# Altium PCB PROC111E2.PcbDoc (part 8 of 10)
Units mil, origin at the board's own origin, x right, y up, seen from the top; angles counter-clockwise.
Board outline 7700 x 2300 mil, 6 copper layers (Top Layer, GND 1, SIG 1, SIG 2, GND 2, Bottom Layer), stack 78.711 mil thick; 767 components, 596 nets, 2755 pads, 1578 vias.
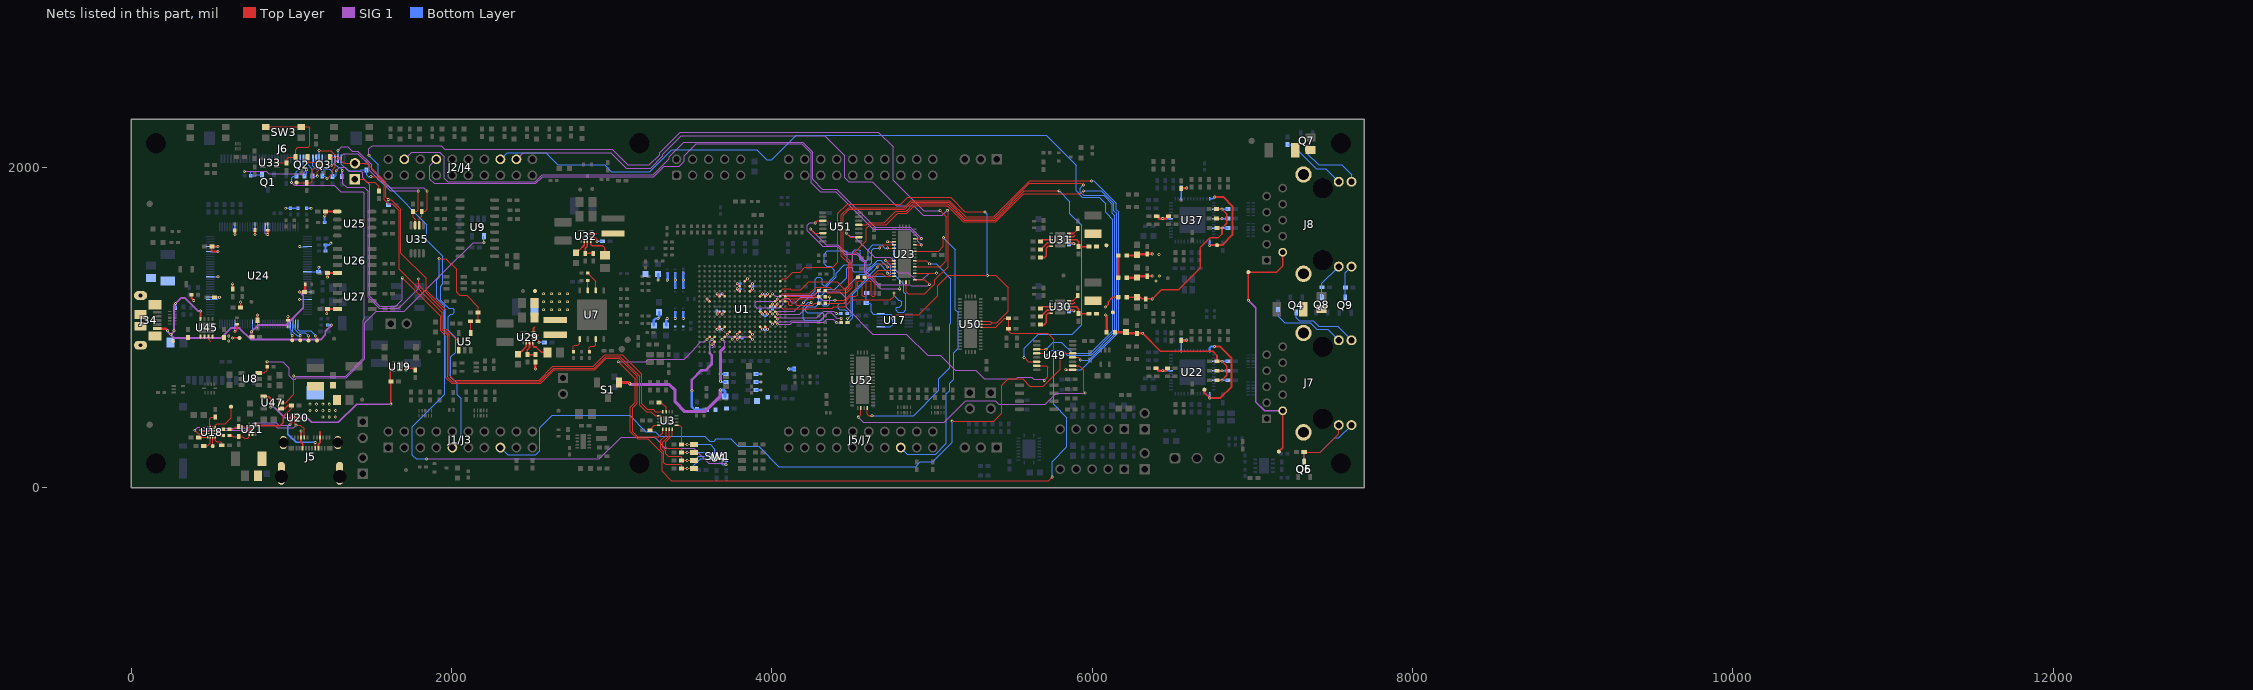
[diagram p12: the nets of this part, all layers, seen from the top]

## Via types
v1: diameter 18, hole 8, Top Layer to Bottom Layer, tented both sides, 1474 vias
v2: diameter 19.68, hole 7.87, Top Layer to Bottom Layer, tented both sides, 104 vias

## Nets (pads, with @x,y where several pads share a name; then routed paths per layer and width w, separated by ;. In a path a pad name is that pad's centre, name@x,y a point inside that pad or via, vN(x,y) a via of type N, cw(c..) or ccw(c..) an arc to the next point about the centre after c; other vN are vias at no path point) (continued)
PR0_PRU0_GPIO3: U1.J17 U23.5 | length 1520.8
  Top Layer w4: U1.J17@4051.07,1130.83 4065.96,1115.93 4114.06,1115.93
  Top Layer w5.3: 4114.06,1115.93 4267.37,1115.93 4270.36,1118.93 4376.37,1118.93 4385.74,1128.3 4454.83,1128.3 4498.62,1172.08 4739.09,1172.08 4762.04,1195.03 v1(4762.04,1215.27) ; v1(4720.59,1535.24) U23.5@4762.24,1535.24
  Bottom Layer w5.3: v1(4720.59,1535.24) 4741.8,1535.24 4765.63,1511.4 4765.63,1327.07 4824.32,1268.39 4824.32,1220.19 4834.95,1209.56 4834.95,1109.8 4821.54,1096.38 4785.96,1096.38 4775,1107.34 4775,1121.6 4780,1126.6 4793.49,1126.6 4809.6,1142.71 4809.6,1159.77 4798.17,1171.21 4792.65,1171.21 4761.31,1202.54 4761.31,1214.54 v1(4762.04,1215.27)
PR0_PRU0_GPIO3_MUX: J2/J4.19 U23.35 | length 3903.5
  Top Layer w5.3: U23.35@4892.17,1554.92 v1(4933.82,1554.92)
  SIG 1 w4.75: J2/J4.19@1704.17,2050 1749.17,2095 1925,2095 1952.52,2067.48 1952.52,1931.18 1974.46,1909.24 2521.06,1909.24 2566.14,1954.33 3259.33,1954.33 3358.59,2053.59 3358.59,2064.84 3449.94,2156.19 4191.54,2156.19 4255,2092.73 4255,1924.04 4315.04,1864 4404.5,1864 4643.67,1624.83 4863.91,1624.83 v1(4933.82,1554.92)
PR0_PRU0_GPIO4: U1.K16 U23.6 | length 1519.2
  Top Layer w5.3: v1(4670.59,1495.87) 4690.28,1515.55 U23.6@4762.24,1515.55
  Top Layer w10: U1.K16@4019.57,1099.33 v1(4035.32,1083.58)
  SIG 1 w4.75: v1(4035.32,1083.58) 4171.86,1083.58 v1(4244.93,1156.66)
  Bottom Layer w5.3: v1(4244.93,1156.66) 4226.95,1156.66 4195.86,1125.57 4195.86,1052.83 4204.94,1043.75 4310.25,1043.75 4321.85,1055.35 4321.85,1083.42 4312.51,1092.76 4219.07,1092.76 4211.79,1100.03 4211.79,1121.09 4220.2,1129.5 4273.31,1129.5 4291.03,1147.23 4291.03,1229.74 4312.18,1250.88 4336.11,1250.88 4400.6,1315.37 4400.6,1339.3 4452.05,1390.76 4609.04,1390.76 4623.28,1405 4623.28,1482.76 4636.39,1495.87 v1(4670.59,1495.87)
PR0_PRU0_GPIO4_MUX: J2/J4.17 U23.33 | length 3771.4
  Top Layer w5.3: U23.33@4892.17,1515.55 v1(4934.43,1515.55)
  SIG 1 w4.75: J2/J4.17@1904.17,2050 1863.41,2009.24 1863.41,1926.94 1891.16,1899.19 2525.22,1899.19 2568.25,1942.22 3261.43,1942.22 3326.48,2007.27 3421.87,2007.27 3451.39,2036.79 3451.39,2071.86 3525.68,2146.14 4187.37,2146.14 4244.93,2088.58 4244.93,1903.06 4300.49,1847.5 4399,1847.5 4631.72,1614.78 4859.05,1614.78 4911.11,1562.72 4911.11,1538.87 v1(4934.43,1515.55)
PR0_PRU0_GPIO5: U1.G17 U49.4 | length 4282.4
  Top Layer w4: U1.G17@4051.07,1193.82 4066.82,1209.57 4114.06,1209.57
  Top Layer w5.3: 4114.06,1209.57 4233.8,1209.57 4276.4,1252.16 4360,1252.16 4377.29,1234.87 4468.46,1234.87 4490.12,1256.53 4490.12,1412.6 4444.48,1458.25 4444.48,1699.98 4482.35,1737.85 4828.85,1737.85 4872.76,1781.76 5102.38,1781.76 5204.14,1680.01 5388.26,1680.01 5608,1899.74 5935.26,1899.74 v1(5945,1890) ; U49.4@5652.8,838.02 5696.58,838.02 v1(5711.38,823.23)
  Bottom Layer w5.3: v1(5711.38,823.23) 5745.7,857.55 5814.73,857.55 5845,827.28 5993.25,827.28 6141.42,975.45 6141.42,1697.14 6125.06,1713.5 6125.06,1769.96 6070.69,1824.33 5945.45,1824.33 5924.62,1845.16 5924.62,1869.62 v1(5945,1890)
PR0_PRU0_GPIO5_MUX: J2/J4.13 U49.3 | length 5659.9
  Top Layer w5.3: U49.3@5652.8,863.61 v1(5711.38,863.61)
  Bottom Layer w5.3: J2/J4.13@2304.17,2050 2345.21,2091.04 2587.3,2091.04 2663.17,2015.17 2954.83,2015.17 2996.5,1973.5 3237,1973.5 3374.75,2111.25 3906.14,2111.25 3968.7,2048.69 3999.85,2048.69 4152.49,2201.32 5711.87,2201.32 5899.18,2014.02 5899.18,1852.75 5938.19,1813.73 6043.16,1813.73 6083.45,1773.44 6083.45,1719.28 6129.52,1673.21 6129.52,1531.91 6129.4,1531.79 6129.4,978.42 5988.86,837.88 5877.94,837.88 5807.09,908.73 5756.49,908.73 v1(5711.38,863.61)
PR0_PRU0_GPIO6: U1.K15 U23.7 | length 1517.1
  Top Layer w5.3: v1(4720.59,1495.87) U23.7@4762.24,1495.87
  Top Layer w10: U1.K15@3988.08,1099.33 v1(4003.83,1083.58)
  SIG 1 w4.75: v1(4003.83,1083.58) 4020.24,1100 4140.09,1100 v1(4196.74,1156.66)
  Bottom Layer w5.3: v1(4196.74,1156.66) 4270.24,1230.15 4270.24,1302.02 4281.65,1313.43 4300,1313.43 4312.89,1300.54 4312.89,1270.44 4321.85,1261.48 4331.72,1261.48 4390,1319.76 4390,1358.24 4366.43,1381.81 4341.25,1381.81 4325,1398.06 4325,1458.62 4345.5,1479.12 4461.67,1479.12 4469.35,1471.45 4469.35,1413.42 4477.77,1405 4496.97,1405 4504.23,1412.26 4504.23,1474.23 4516.68,1486.68 4543.64,1486.68 4550,1480.32 4550,1425.91 4560.91,1415 4590,1415 4600.62,1425.62 4600.62,1486.68 4629.34,1515.39 4685.27,1515.39 4704.79,1495.87 v1(4720.59,1495.87)
PR0_PRU0_GPIO6_MUX: J5/J7.48 U23.31 | length 1927.2
  Top Layer w5.3: U23.31@4892.17,1476.18 5040,1476.18 5070,1506.18 v1(5070,1560.88)
  Bottom Layer w5.3: J5/J7.48@4804.17,250 4845.21,208.96 5021.17,208.96 5089.4,277.19 5089.4,584.4 5109.02,604.02 5109.02,651.44 5135.6,678.02 5135.6,843.47 5161.9,869.76 5161.9,1094.21 5145.12,1110.98 5145.12,1485.75 v1(5070,1560.88)
PR0_PRU0_GPIO8: U1.G15 U49.7 | length 2172.1
  Top Layer w5.3: U49.7@5652.8,761.25 5713.35,761.25 5722.21,752.39 5722.21,691.43 v1(5700.39,669.61)
  Top Layer w10: U1.G15@3988.08,1193.82 v1(4003.83,1209.57)
  SIG 1 w4.75: v1(4003.83,1209.57) 4019.2,1194.19 4041.69,1194.19 4047.02,1199.52 4262.49,1199.52 4286.06,1223.08 4422.81,1223.08 4462.51,1183.37 4462.51,1125.71 4630.59,957.64 4839.34,957.64 4971.11,825.87 5050.22,825.87 5142.89,733.2 5273.18,733.2 5326.71,679.67 5526.97,679.67 5535.37,688.07 5622.92,688.07 5635,676 5694,676 v1(5700.39,669.61)
PR0_PRU0_GPIO8_MUX: U49.6 U51.13 | length 2884
  Top Layer w5.3: U51.13@4542.2,1640.71 4590,1640.71 4603.53,1654.23 4700.73,1654.23 4772,1725.5 4837.5,1725.5 4883.16,1771.16 5097.99,1771.16 5199.75,1669.41 5392.65,1669.41 5576.49,1853.25 v1(5793.08,1853.25) ; v1(5574.59,812.43) 5600.18,786.84 U49.6@5652.8,786.84
  Bottom Layer w5.3: v1(5574.59,812.43) 5574.59,869.86 5663.53,958.8 5875.3,958.8 5933.8,1017.3 5933.8,1638 5860.24,1711.56 5860.24,1786.09 v1(5793.08,1853.25)
PR0_PRU0_GPIO9: U1.F17 U49.9 | length 4170
  Top Layer w4: U1.F17@4051.07,1225.32 4066.82,1241.06 4113.02,1241.06 4114.06,1240.02
  Top Layer w5.3: 4114.06,1240.02 4119.55,1234.53 4178.39,1234.53 4228.04,1284.18 4376.58,1284.18 4376.91,1284.5 4393.08,1284.5 4393.4,1284.18 4406.06,1284.18 4444.77,1245.47 4464.07,1245.47 4479.52,1260.92 4479.52,1399.39 4433.88,1445.04 4433.88,1704.37 4477.96,1748.45 4821.38,1748.45 4865.29,1792.36 5106.77,1792.36 5208.53,1690.61 5383.87,1690.61 5608.26,1915 v1(5995,1915) ; v1(5835,735.66) U49.9@5877.2,735.66
  Bottom Layer w5.3: v1(5835,735.66) 5931.61,735.66 6165,969.05 6165,1721.33 6150.65,1735.68 6150.65,1774.35 6010,1915 v1(5995,1915)
PR0_PRU0_GPIO9_MUX: U49.10 U52.40 | length 1815.2
  Top Layer w5.3: v1(4538.82,440) 4555.16,456.34 U52.40@4555.16,496.77 ; U49.10@5877.2,761.25 5920,761.25 5948,733.25 5948,597.48 v1(5955.48,590)
  SIG 1 w4.75: v1(4538.82,440) 4569.96,408.86 5075.37,408.86 5208.51,542 5393.5,542 5415.61,519.89 5705.32,519.89 5775.43,590 v1(5955.48,590)
PR0_PRU0_GPIO10: R286.1 U49.12 | length 3518.1
  Top Layer w5.3: R286.1@4331.94,1231.79 4346.57,1217.16 4466.85,1217.16 4500.72,1251.03 4500.72,1455.1 4588.41,1542.79 4588.41,1618.54 4612.29,1642.41 4714.55,1642.41 4784.96,1712.82 4840.58,1712.82 4888.32,1760.56 5093.6,1760.56 5195.36,1658.81 5397.04,1658.81 5571.96,1833.72 5924.62,1833.72 v1(5944.14,1853.25) ; U49.12@5877.2,812.43 5911.5,812.43 v1(5927.62,796.31)
  Bottom Layer w5.3: v1(5927.62,796.31) 5977.28,796.31 6152.02,971.06 6152.02,1711.6 6135.66,1727.96 6135.66,1774.35 6056.76,1853.25 v1(5944.14,1853.25)
PR0_PRU0_GPIO10_MUX: J1/J3.8 U49.13 | length 4473.9
  Top Layer w5.3: v1(5125,414.7) 5385,414.7 5435,464.7 5435,638.6 5475,678.6 5564.85,678.6 5609.88,633.56 5694.94,633.56 5800,738.62 5800,812.74 5825.28,838.02 U49.13@5877.2,838.02
  Bottom Layer w5.3: J1/J3.8@2304.17,250 2349.17,205 2524.5,205 2550.5,231 2550.5,374.33 2627.03,450.85 3111.89,450.85 3212.74,350 3270.02,350 3300.12,319.9 3581.55,319.9 3610.74,290.71 3637.83,290.71 3651.65,304.52 3741.56,304.52 3788.08,258.01 3916.05,258.01 4042.86,131.2 4896.2,131.2 4927.32,162.32 5004.51,162.32 5125,282.81 v1(5125,414.7)
PR0_PRU0_GPIO10_R: R286.2 U1.G18 | length 225.7
  Top Layer w4: U1.G18@4082.57,1193.82 4114.06,1193.82
  Top Layer w5.3: 4114.06,1193.82 4252.62,1193.82 4290.6,1231.79 R286.2@4292.57,1231.79
PR0_PRU0_GPIO11: R75.1 U23.11 | length 629.5
  Top Layer w5.3: v1(4709.76,1417.13) U23.11@4762.24,1417.13
  Bottom Layer w5.3: R75.1@4473.25,1029.85 4504.23,1060.84 4504.23,1207.24 4615.86,1318.86 4728.68,1318.86 4740.77,1330.96 4740.77,1386.12 v1(4709.76,1417.13)
PR0_PRU0_GPIO11_MUX: U23.28 U52.42 | length 1556
  Top Layer w5.3: U52.42@4594.53,496.77 4594.53,459.12 4604.81,448.84 v1(4624.81,448.84) ; U23.28@4892.17,1417.13 4964.13,1417.13 v1(4983.82,1397.44)
  Bottom Layer w5.3: v1(4624.81,448.84) 4883.84,448.84 5042.04,607.04 5042.04,680 5109.61,747.56 5109.61,1019.96 5117.27,1027.62 5117.27,1305.63 5026.09,1396.81 4984.45,1396.81 v1(4983.82,1397.44)
PR0_PRU0_GPIO11_R: R75.2 U1.M16 | length 439.5
  Top Layer w10: U1.M16@4019.57,1036.34 v1(4035.32,1020.59)
  SIG 1 w4: v1(4035.32,1020.59) 4113.53,1020.59 4114.06,1021.12
  SIG 1 w4.75: 4114.06,1021.12 4125.51,1032.57 4323.77,1032.57 4341.27,1050.07 4383.67,1050.07 v1(4403.87,1029.87)
  Bottom Layer w5.3: v1(4403.87,1029.87) R75.2@4431.93,1029.87
PR0_PRU0_GPIO12: R76.1 U23.12 | length 538.7
  Top Layer w5.3: R76.1@4471.93,1029.87 v1(4471.93,1056.95) ; v1(4659.76,1377.76) 4679.45,1397.44 U23.12@4762.24,1397.44
  Bottom Layer w5.3: v1(4471.93,1056.95) 4475.96,1056.95 4493.63,1074.62 4493.63,1211.63 v1(4659.76,1377.76)
PR0_PRU0_GPIO12_MUX: J1/J3.5 U23.26 | length 6810.1
  Top Layer w5.3: U23.26@4892.17,1377.76 5051.06,1377.76 5089.52,1416.23 5089.52,1690.48 v1(5050,1730)
  SIG 1 w4.75: v1(1483,2075) 1483,2114.79 1502.43,2134.22 1934.16,2134.22 1956.7,2111.69 3002.04,2111.69 3098.55,2015.18 3233.36,2015.18 3297.74,2079.55 3297.74,2090.05 3427.69,2220 4665,2220 4756.5,2128.5 4756.5,1920.5 4947,1730 v1(5050,1730)
  Bottom Layer w5.3: v1(1483,2075) 1541,2017 1541,1926.77 1584.27,1883.5 1603,1883.5 1845,1641.5 1845,1545 1944.52,1445.48 1944.52,1271.36 1931.78,1258.62 1931.78,1169.79 1980.4,1121.17 2005.77,1121.17 2017.21,1109.73 2017.21,1093.56 2005.34,1081.69 1992.81,1081.69 1977.82,1066.71 1977.82,981.22 2023.54,935.51 2023.54,844.12 1995,815.58 1995,689.99 2035,649.99 2035,580.37 2059.52,555.84 2059.52,305.35 J1/J3.5@2004.17,250
PR0_PRU0_GPIO12_R: R76.2 U1.M15 | length 521.3
  Top Layer w5.3: R76.2@4432.56,1029.87 v1(4432.56,1056.95)
  Top Layer w10: U1.M15@3988.08,1036.34 v1(4003.83,1020.59)
  SIG 1 w4.75: v1(4003.83,1020.59) 4019.95,1036.71 4113.69,1036.71 4119.6,1042.62 4299.62,1042.62 4347.89,1090.9 4370.68,1090.9 4404.62,1056.95 v1(4432.56,1056.95)
PR0_PRU0_GPIO13: R77.1 U23.13 | length 818.2
  Top Layer w5.3: R77.1@4331.94,1191.33 v1(4360,1191.33) ; v1(4720.59,1377.76) U23.13@4762.24,1377.76
  Bottom Layer w5.3: v1(4360,1191.33) 4360,1146.68 4348.32,1135 4320.39,1135 4307.08,1148.31 4307.08,1197.84 4346.45,1237.21 4393.4,1237.21 4467.17,1310.97 4467.17,1370.24 4473.67,1376.74 4497.43,1376.74 4504.17,1370 4504.17,1354.93 4511.92,1347.18 4586.06,1347.18 4658.88,1420 4678.35,1420 v1(4720.59,1377.76)
PR0_PRU0_GPIO13_MUX: U23.24 U51.10 | length 949
  Top Layer w5.3: v1(4464,1589.53) 4489.59,1563.94 U51.10@4542.2,1563.94 ; U23.24@4892.17,1338.39 5026.38,1338.39 v1(5026.97,1338.98)
  SIG 1 w4.75: v1(4464,1589.53) 4484.37,1569.15 4510.85,1569.15 4642.75,1437.25 4736.95,1437.25 4769.71,1404.49 4769.71,1360.78 4789.65,1340.83 4851.94,1340.83 4893.32,1299.45 4941.79,1299.45 4981.16,1338.82 5026.82,1338.82 v1(5026.97,1338.98)
PR0_PRU0_GPIO13_R: R77.2 U1.H17 | length 253.5
  Top Layer w4: U1.H17@4051.07,1162.32 4067.21,1178.46 4114.06,1178.46
  Top Layer w5.3: 4114.06,1178.46 4257.13,1178.46 4270,1191.33 R77.2@4292.57,1191.33
PR0_PRU0_GPIO14: R78.1 U23.14 | length 204
  Top Layer w5.3: R78.1@4576.85,1313.21 4620,1313.21 4664.86,1358.07 U23.14@4762.24,1358.07
PR0_PRU0_GPIO14_MUX: U23.22 U51.6 | length 1124
  Top Layer w5.3: v1(4239.59,1615.12) 4265.18,1589.53 U51.6@4317.8,1589.53 ; U23.22@4892.17,1299.02 4954.13,1299.02 v1(4983.82,1269.33)
  SIG 1 w4.75: v1(4239.59,1615.12) 4337.74,1516.97 4410.95,1516.97 4462.23,1465.69 4532.88,1465.69 4590.05,1408.51 4590.05,1347.98 4671.31,1266.72 4861.82,1266.72 4869.29,1259.25 4973.74,1259.25 v1(4983.82,1269.33)
PR0_PRU0_GPIO14_R: R78.2 U1.H16 | length 1007.6
  Top Layer w5.3: v1(4393.4,1170) 4449.67,1170 4525,1245.33 4525,1300.74 R78.2@4537.48,1313.21
  Top Layer w10: U1.H16@4019.57,1162.32 v1(4035.32,1178.07)
  SIG 1 w4.75: v1(4035.32,1178.07) 4034.58,1178.07 4019.14,1162.63 3903.65,1162.63 3893.96,1152.94 3893.96,1132.7 3905,1121.66 4047.91,1121.66 4071.29,1145.03 4071.29,1172.13 4080.07,1180.91 4101.11,1180.91 4127.02,1155 4144.29,1155 4178.76,1189.47 4298.35,1189.47 4317.82,1170 v1(4393.4,1170)
PR0_PRU0_GPIO15: R79.1 U23.15 | length 630.8
  Top Layer w5.3: v1(4720.59,1338.39) U23.15@4762.24,1338.39
  Bottom Layer w5.3: R79.1@4469.35,1086.88 4469.35,1100 4457.97,1111.38 4424.44,1111.38 4415,1120.82 4415,1143.26 4422.22,1150.48 4451.81,1150.48 4461.67,1160.33 4461.67,1245.15 4547.65,1331.13 4585,1331.13 4651.15,1397.28 4671.44,1397.28 4720.59,1348.13 v1(4720.59,1338.39)
PR0_PRU0_GPIO15_MUX: J2/J4.12 U23.20 | length 3902.5
  Top Layer w5.3: U23.20@4837.05,1283.27 4837.05,1222.45 4849.93,1209.57 4952.79,1209.57 5017.02,1273.8 5017.02,1297.5 5100.12,1380.6 5100.12,1726.43 v1(5095,1731.55)
  SIG 1 w4.75: J2/J4.12@2404.17,2050 2445.21,2091.04 2993.09,2091.04 3089.6,1994.53 3241.91,1994.53 3318.39,2071 3318.39,2081.49 3433.29,2196.39 4329.64,2196.39 4454.98,2071.05 4454.98,1934.26 4480,1909.24 4626.07,1909.24 4776.68,1758.62 4886.03,1758.62 4943.54,1701.11 5064.55,1701.11 v1(5095,1731.55)
PR0_PRU0_GPIO15_R: R79.2 U1.L16 | length 444.1
  Top Layer w10: U1.L16@4019.57,1067.83 v1(4035.32,1052.09)
  SIG 1 w4.75: v1(4035.32,1052.09) 4043.24,1060 4280,1060 4322.33,1102.33 4386.47,1102.33 v1(4401.92,1086.88)
  Bottom Layer w5.3: v1(4401.92,1086.88) R79.2@4429.98,1086.88
PR0_PRU0_GPIO16: R80.1 U23.16 | length 943.9
  Top Layer w5.3: R80.1@4331.94,1151.33 4332.79,1150.48 4447.03,1150.48 4489.83,1193.28 4523.26,1193.28 4535.6,1205.63 4535.6,1285 4543.45,1292.85 4557.03,1292.85 4563.14,1286.74 4563.14,1200.44 4569.39,1194.19 4582.16,1194.19 4589.07,1201.1 4589.07,1285.11 4596.81,1292.85 4611,1292.85 4619.2,1284.65 4619.2,1200.29 4625.94,1193.54 4639.04,1193.54 4645.5,1200 4645.5,1320.15 4660.35,1335 4689.46,1335 4705.75,1318.7 U23.16@4762.24,1318.7
PR0_PRU0_GPIO16_MUX: U23.18 U51.3 | length 951.9
  Top Layer w5.3: v1(4270,1652.62) 4283.68,1666.3 U51.3@4317.8,1666.3 ; v1(4797.68,1241.01) U23.18@4797.68,1283.27
  SIG 1 w4.75: v1(4270,1652.62) 4234.29,1652.62 4220,1638.33 4220,1602.91 4315.98,1506.92 4406.78,1506.92 4458.07,1455.64 4528.71,1455.64 4580,1404.35 4580,1340.81 4679.81,1241.01 v1(4797.68,1241.01)
PR0_PRU0_GPIO16_R: R80.2 U1.H18 | length 285.1
  Top Layer w5.3: U1.H18@4082.57,1162.32 4099.55,1162.32 4103.77,1158.1 4103.77,1141.12 4107.76,1137.13 4122.13,1137.13 4127.72,1142.72 4127.72,1162.11 4133.48,1167.86 4144.81,1167.86 4150,1162.67 4150,1142.13 4155,1137.13 4253.02,1137.13 4267.22,1151.33 R80.2@4292.57,1151.33
QSPI0_D2: R29.1 U7.3 | length 61.6
  Top Layer w5.3: R29.1@2849.68,1293.54 2849.68,1232.39 U7.3@2850,1232.08
QSPI0_D3: R30.1 U7.7 | length 109.1
  Top Layer w5.3: R30.1@2860,848.65 2860,876.52 2866.97,883.49 2891.34,883.49 2900,892.15 U7.7@2900,926.92
QSPI_D0: R27.1 U7.5 | length 105.7
  Top Layer w5.3: R27.1@2760,848.65 2760,881.33 2768.06,889.39 2786.59,889.39 2800,902.8 U7.5@2800,926.92
QSPI_D1: R28.1 U7.2 | length 128
  Top Layer w5.3: R28.1@2849.68,1339.27 2900,1288.95 U7.2@2900,1232.08
RESETN_PB: Q2.2 R178.1 SW3.2 SW3.4 U33.2 | length 678.4
  Top Layer w5.3: SW3.2@839.76,2252.28 SW3.4@1060.24,2252.28 1106.81,2252.28 1114.09,2245 1114.09,2135 1103.05,2123.95 1038.54,2123.95 1024.85,2110.27 Q2.2@1024.85,2064.27 981.22,2064.27 968.08,2051.13 R178.1@968.08,2028.15 U33.2@907.66,2028.15
RGMII1_ICSSM_MUX_EN_GPIO1: R292.2 R294.2 U1.R3 U50.8 | length 5481.9
  Top Layer w5.3: v1(3040,785.56) 3145,680.56 3145,532.3 3115,502.3 3115,350 3160.61,304.39 3224.11,304.39 3313.5,215 3313.5,100.87 3371.2,43.18 5726.76,43.18 v1(5750,66.42) ; U50.8@5303.35,1000.35 5397.83,1000.35 5454.5,1057.02 R292.2@5477.76,1057.02 R294.2@5477.76,992.02 5477.76,976.31 5489.74,964.33 5722.88,964.33 5760,927.2 v1(5760,815.75)
  Top Layer w10: v1(3594.38,926.1) U1.R3@3610.12,941.85
  SIG 1 w4.75: v1(3040,785.56) 3212.81,785.56 3228.06,800.8 3451.39,800.8 3513.8,863.22 3513.8,868.03 3555.76,909.98 3578.26,909.98 v1(3594.38,926.1)
  Bottom Layer w5.3: v1(5750,66.42) 5750,162.32 5842.18,254.5 5842.18,436.97 5760,519.15 v1(5760,815.75)
RGMII1_ICSSM_MUX_SEL_GPIO105: R291.2 R293.2 U1.D17 U17.1 U17.5 U50.9 U50.10 | length 3866.3
  Top Layer w5.3: U1.D17@4051.07,1288.31 4068.04,1305.28 4090.41,1305.28 4130.23,1345.1 4175.07,1345.1 4206.07,1376.1 4380.76,1376.1 4411.7,1407.04 4411.7,1712.17 4469.17,1769.65 4804.94,1769.65 4848.85,1813.56 5115.55,1813.56 5208.39,1720.73 5209.1,1721.45 v1(5330,1721.45) ; v1(4752.96,1057.75) 4776.02,1080.8 4917.18,1080.8 5034.52,1198.14 5034.52,1259.78 5099.74,1325 v1(5345,1325) 5397.09,1325 5474.89,1247.19 5474.89,1100.86 5402.46,1028.43 5374.87,1028.43 ; U50.9@5303.35,1020.04 5366.48,1020.04 5374.87,1028.43 ; U50.10@5303.35,1039.72 5363.57,1039.72 5374.87,1028.43
  Bottom Layer w5.3: R293.2@4591.64,1215.33 4588.62,1212.32 R291.2@4588.62,1152.36 4610,1152.36 4618.69,1143.67 4618.69,1097.35 4632.92,1083.12 U17.5@4680.08,1083.12 4740.77,1083.12 4752.86,1071.02 4752.86,1057.85 v1(4752.96,1057.75) 4752.84,1057.62 4752.84,1017.37 4739.85,1004.38 U17.1@4680.08,1004.38 ; v1(5330,1721.45) 5345,1706.45 v1(5345,1325)
RJ45_1_LED1_GREEN: J7.11 R224.2 | length 482.1
  Bottom Layer w5.3: R224.2@7160.2,1111.38 7160.2,1070.65 7200.85,1030 7360,1030 7401.78,988.22 7470.62,988.22 J7.11@7539.08,919.76
RJ45_1_LED1_YELLOW: J7.12 Q4.3 | length 433.3
  Bottom Layer w5.3: Q4.3@7274.1,1090.04 7274.1,1059.48 7291.58,1041.99 7379.47,1041.99 7414.47,1006.99 7531.77,1006.99 J7.12@7619,919.76
RJ45_1_LED2_GREEN: J7.13 Q5.3 R226.1 | length 377.3
  Top Layer w5.3: Q5.3@7324,160.9 R226.1@7324,221.46 7424.43,221.46 7539.08,336.1 J7.13@7539.08,390.24
RJ45_1_LED2_YELLOW: J7.14 Q6.3 R228.1 | length 425.5
  Bottom Layer w5.3: Q6.3@7324,160.9 R228.1@7324,221.46 7424.43,221.46 7512.97,310 7538.76,310 J7.14@7619,390.24
RJ45_1_VCC: J7.2 J8.2 TP21.1 TP22.1 | length 1601.1
  Top Layer w10: v1(6975,1170) TP21.1@6975,1345.45 7150.65,1345.45 7189.08,1383.88 J8.2@7189.08,1470 ; TP22.1@7165,225 7189.08,249.08 J7.2@7189.08,480
  SIG 1 w10: v1(6975,1170) 7021.66,1123.34 7021.66,535 7076.66,480 J7.2@7189.08,480
RJ45_2_LED1_GREEN: J8.11 R230.2 | length 415
  Bottom Layer w5.3: R230.2@7220,2141.38 7247.83,2141.38 7399.21,1990 7458.84,1990 J8.11@7539.08,1909.76
RJ45_2_LED1_YELLOW: J8.12 Q7.3 | length 407.6
  Bottom Layer w5.3: Q7.3@7340,2117.76 7340,2088.61 7413.61,2015 7557.14,2015 7619,1953.14 J8.12@7619,1909.76
RJ45_2_LED2_GREEN: J8.13 Q8.3 R232.1 | length 235.9
  Bottom Layer w5.3: Q8.3@7433.87,1187.91 R232.1@7433.87,1251.28 7433.87,1275.03 J8.13@7539.08,1380.24
RJ45_2_LED2_YELLOW: J8.14 Q9.3 R234.1 | length 209.6
  Bottom Layer w5.3: Q9.3@7580.33,1186.64 R234.1@7580.33,1250 7580.33,1341.56 J8.14@7619,1380.24
SD_PWR_EN: R39.2 U8.3 U9.4 | length 2063
  Top Layer w5.3: U8.3@795.16,716 829.3,716 847.55,734.25 R39.2@847.55,754.8 v1(847.55,785.81)
  SIG 1 w4.75: v1(847.55,785.81) 944.19,785.81 985,745 985,698 1005.73,677.28 1021.67,677.28 1029.5,685.1 1339.72,685.1 1458.14,803.52 1458.14,1028.79 1529.57,1100.21 1704.67,1100.21 1945,1340.54 1945.21,1340.54 2135,1530.33 v1(2201.37,1530.33)
  Bottom Layer w5.3: v1(2201.37,1530.33) U9.4@2201.37,1570.16
SHIELD1: C229.2 J5.1 J5.2 J5.3 J5.4 R32.1
SHIELD2: C235.2 J7.15 J7.16 R254.1
SHIELD3: C247.2 J8.15 J8.16 R255.1
SHIELD4: C230.2 J34.6 J34.7 J34.8 J34.9 J34.10 J34.11 R253.1
SOC_TA_I2C3_SCL: J6.36 R192.1 U35.7 | length 977.1
  Top Layer w5.3: U35.7@1771.58,1637.6 1771.58,1675.59 1758.28,1688.89 R192.1@1758.28,1724.72 1780.75,1724.72 1790.94,1734.91 v1(1790.94,1852.17)
  SIG 1 w5.3: v1(1250,2010.39) 1325.11,2085.5 1414.6,2085.5 1485.5,2014.6 1485.5,1983.2 1616.53,1852.17 v1(1790.94,1852.17)
  Bottom Layer w5.3: v1(1250,2010.39) 1250.75,2011.14 J6.36@1250.75,2053.35
SOC_TA_I2C3_SDA: J6.38 R190.1 U35.6 | length 996.7
  Top Layer w5.3: U35.6@1797.17,1637.6 1797.17,1678.19 1813.28,1694.3 R190.1@1813.28,1724.72 1834.22,1724.72 1846.52,1737.03 v1(1846.52,1852.17)
  SIG 1 w5.3: v1(1290.12,2105.5) 1314.14,2129.52 1351.98,2129.52 1380.03,2101.47 1413.62,2101.47 1500.5,2014.59 1500.5,1987.29 1615.64,1872.14 1826.55,1872.14 v1(1846.52,1852.17)
  Bottom Layer w5.3: J6.38@1290.12,2053.35 v1(1290.12,2105.5)
SOP0_SW: R14.2 SW1.8 U3.2 U4.6 | length 617
  Top Layer w5.3: U3.2@3338.21,363.58 3338.21,327.25 3305,294.04 3305,243.34 3325.5,222.84 3325.5,155.47 3336.15,144.82 3429.69,144.82 3435.55,138.97 R14.2@3435.55,119.51 v1(3470.3,119.51) SW1.8@3512.3,119.51
  Bottom Layer w5.3: v1(3470.3,119.51) 3494.01,119.51 3554.41,179.91 U4.6@3618.83,179.91
SOP1_SW: R15.2 SW1.7 U3.3 U4.7 | length 540.9
  Top Layer w5.3: U3.3@3357.9,363.58 3357.9,324.9 3317.5,284.5 3317.5,251 3337.66,230.85 3337.66,209.85 3352.68,194.82 3429.69,194.82 3435.55,188.97 R15.2@3435.55,169.51 v1(3470.3,169.51) SW1.7@3512.3,169.51
  Bottom Layer w5.3: v1(3470.3,169.51) 3516.01,169.51 3542.15,195.65 U4.7@3618.83,195.65
SOP2_SW: R16.2 SW1.6 U3.4 U4.8 | length 480.1
  Top Layer w5.3: U3.4@3377.58,363.58 3377.58,327.08 3336,285.5 3336,255 3346.18,244.82 3429.69,244.82 3435.55,238.97 R16.2@3435.55,219.51 v1(3470.3,219.51) SW1.6@3512.3,219.51
  Bottom Layer w5.3: v1(3470.3,219.51) 3581.42,219.51 3589.52,211.4 U4.8@3618.83,211.4
SOP3_SW: R17.2 SW1.5 U3.5 U4.9 | length 426
  Top Layer w5.3: U3.5@3403.17,389.17 3422,389.17 3435.55,375.62 R17.2@3435.55,269.51 v1(3470.3,269.51) SW1.5@3512.3,269.51
  Bottom Layer w5.3: v1(3470.3,269.51) 3612.96,269.51 3642.45,240.02 U4.9@3642.45,219.28
SOP_DRIVE_OEN_R: R18.1 U5.4 | length 74.2
  Top Layer w5.3: R18.1@2117.18,1039.07 2118.71,1037.54 U5.4@2118.71,965.53
SOP_DRIVER_OEN: R18.2 R20.1 U4.1 U4.16 | length 4033.2
  Top Layer w5.3: v1(1921.18,1429.68) 1962.46,1429.68 2030,1362.14 2030,1219.59 2050,1199.59 2092.36,1199.59 2164.43,1127.52 R20.1@2164.43,1094.07 R18.2@2164.43,1039.07
  SIG 1 w4.75: v1(1843,178.5) 2922.67,178.5 3058,313.83 3266.41,313.83 3334.73,245.5 3512.39,245.5 3605.89,152 3703.72,152 v1(3713.32,142.41)
  Bottom Layer w5.3: v1(1843,178.5) 1778.5,178.5 1754.13,202.87 1754.13,379.85 1903.09,528.8 1955.64,581.36 1955.64,1130.93 1905.48,1181.1 1905.48,1298.97 1921.18,1314.67 v1(1921.18,1429.68) ; U4.1@3689.69,158.25 3689.69,146.32 3693.61,142.41 v1(3713.32,142.41) U4.16@3713.32,164.16
TA_GPIO1: J6.30 Q3.1 R185.2 | length 364.2
  Top Layer w5.3: v1(1221.4,1930) 1252.5,1961.1 1252.5,1982 1272.5,2002 1272.5,2053.96 1262.19,2064.27 Q3.1@1238.52,2064.27
  Bottom Layer w5.3: J6.30@1132.64,2053.35 1132.64,2010 1152.64,1990 1172.01,1990 1190.9,1971.1 R185.2@1190.9,1944.53 1191.59,1943.84 1207.56,1943.84 v1(1221.4,1930)
TA_GPIO2: J6.31 R184.2 TP18.1 | length 259.7
  Top Layer w5.3: TP18.1@1030,1905 1031.38,1903.62 R184.2@1094.86,1903.62 1118.66,1903.62 1130.5,1915.46 1130.5,1980.36 v1(1160.53,2010.39)
  Bottom Layer w5.3: J6.31@1152.32,2053.35 1152.32,2018.6 v1(1160.53,2010.39)
TA_GPIO3: J1.2 J6.32 R183.2 U5.1 | length 1831.2
  Top Layer w5.3: v1(1172.01,2105) 1245,2105 1325,2025 J1.2@1395.54,2025 1468.7,2025 1587.99,1905.71 1587.99,1814.55 v1(1603.77,1798.77) 1620.75,1798.77 1681.34,1738.18 1681.34,1464.38 1839.67,1306.04 1839.67,1231.54 1961.8,1109.42 1961.8,993.2 2043.91,911.09 U5.1@2043.91,857.27
  Bottom Layer w5.3: J6.32@1172.01,2053.35 v1(1172.01,2105) ; R183.2@1603.77,1765 v1(1603.77,1798.77)
TA_GPIO3_PD: J1.1 R21.2 | length 195.5
  Top Layer w5.3: J1.1@1395.54,1925 1451.5,1925 1469,1907.5 1518.67,1907.5 1545,1881.17 R21.2@1545,1853.25
TA_GPIO4: J6.33 R182.2 U3.1 | length 4222.7
  Top Layer w5.3: v1(1690.74,1309.56) 1930,1070.3 1930,978.8 1963.29,945.51 1963.29,685.87 1999.14,650.03 2554.71,650.03 2640.35,735.66 2893.84,735.66 2965.13,806.95 3047.2,806.95 3160,694.16 3160,528.06 3130,498.06 3130,350 3162.82,317.18 3292.18,317.18 3318.53,343.53 U3.1@3318.53,363.58
  SIG 1 w5.3: v1(1279,1978.5) 1301.5,2001 1336.5,2001 1361,1976.5 1433.5,1976.5 1444,1966 1444,1934.5 1488.5,1890 1488.5,1194.16 1550.93,1131.74 1648.84,1131.74 1690.74,1173.64 v1(1690.74,1309.56)
  Bottom Layer w5.3: J6.33@1191.69,2053.35 1191.69,2000 1203.9,1987.8 1237.7,1987.8 1256.5,1969 1256.5,1945.12 R182.2@1255,1943.62 1273.62,1943.62 1279,1949 v1(1279,1978.5)
TA_I2C_SCL: J6.37 R191.1 U3.12 | length 3857.8
  Top Layer w5.3: v1(1793.39,1302.62) 1793.39,1262.84 1951.2,1105.03 1951.2,988.81 1984.49,955.52 1984.49,702.32 2015.59,671.23 2545.93,671.23 2631.57,756.86 2885.06,756.86 2956.35,828.15 3064.42,828.15 3185.98,706.59 3185.98,523.5 3221.26,488.21 3257.55,488.21 3271.94,473.82 U3.12@3318.53,473.82
  SIG 1 w5.3: v1(1319,1980) 1319,1898.5 1343,1874.5 1454.5,1874.5 1477.9,1851.1 1477.9,1189.77 1546.53,1121.14 1669.72,1121.14 1793.39,1244.8 v1(1793.39,1302.62)
  Bottom Layer w5.3: J6.37@1270.43,2053.35 1270.43,2019.07 1290.5,1999 1300,1999 v1(1319,1980) 1312.52,1973.52 R191.1@1312.52,1943.62
TA_I2C_SDA: J6.39 R189.1 U3.13 | length 3418.4
  Top Layer w5.3: v1(1495,1942.32) 1536.39,1942.32 1577.39,1901.32 1577.39,1797.54 1602.96,1771.97 1628.04,1771.97 1670.74,1729.27 1670.74,1362.73 1940.6,1092.87 1940.6,984.42 1973.89,951.13 1973.89,690.26 2003.53,660.63 2550.32,660.63 2635.96,746.26 2889.45,746.26 2960.74,817.55 3053.7,817.55 3175.38,695.87 3175.38,514.62 3215,475 3243.65,475 3270.42,448.23 U3.13@3292.94,448.23
  Bottom Layer w5.3: J6.39@1309.8,2053.35 1309.8,2020.2 1352.5,1977.5 1430.5,1977.5 1436.38,1983.38 R189.1@1468,1983.38 1468,1952.5 1478.18,1942.32 v1(1495,1942.32)
TA_PORZ: J6.27 Q1.1 R180.1 R187.2 | length 663.3
  SIG 1 w5.3: v1(705,1975) 842.56,1975 857.14,1960.43 1068.69,1960.43 v1(1093.27,1985)
  Bottom Layer w5.3: v1(705,1975) 737.44,1975 745.37,1967.07 R180.1@745.37,1947.32 773.09,1947.32 780.77,1955 Q1.1@815.58,1955 ; J6.27@1073.58,2053.35 1073.58,2005 1093.27,1985.32 v1(1093.27,1985) 1093.27,1961.2 1079.84,1947.78 R187.2@1079.84,1945
TA_POWERDOWNZ: J6.26 R188.2 U47.2 | length 2394
  Top Layer w5.3: U47.2@933.63,531 962.79,531 1013.7,581.91 v1(1013.7,696.52)
  SIG 1 w4.75: v1(1000,1905) 1017.5,1887.5 1265.5,1887.5 1305.5,1847.5 1444.59,1847.5 1455.16,1836.93 1455.16,1053.16 1448.09,1046.09 1448.09,807.68 1336.93,696.52 v1(1013.7,696.52)
  Bottom Layer w5.3: v1(1000,1905) 1000,1935 1010,1945 R188.2@1029.84,1945 1029.84,1973.58 1053.9,1997.64 J6.26@1053.9,2053.35
TA_RESETZ: J6.28 Q2.1 R186.2 | length 353.8
  Top Layer w5.3: Q2.1@1099.65,2064.27 1099.94,2063.98 1099.94,2039.74 1107.42,2032.26 1173.98,2032.26 1180.06,2026.19 1180.06,1992.97 1160.53,1973.45 v1(1160.53,1945)
  Bottom Layer w5.3: J6.28@1093.27,2053.35 1093.27,2024.37 1129.84,1987.8 R186.2@1129.84,1945 v1(1160.53,1945)
TCA_ADDR: R10.2 U3.16 | length 64.9
  Top Layer w5.3: R10.2@3238.62,363.58 3264.21,389.17 U3.16@3292.94,389.17
TCA_INTN: R11.2 U3.11 | length 84.6
  Top Layer w5.3: R11.2@3293.62,530.76 3309.37,530.76 3338.21,501.92 U3.11@3338.21,473.82
TM4C129_TCK: TP27.1 U24.100 | length 106
  Top Layer w5.3: TP27.1@1003.9,920 v1(1003.9,948.54)
  Bottom Layer w5.3: U24.100@992.35,1021.22 992.35,987.26 997.01,982.59 997.01,955.43 v1(1003.9,948.54)
TM4C129_TDI: TP29.1 U24.98 | length 161.9
  Top Layer w5.3: TP29.1@1105.9,919 v1(1105.9,947.54)
  Bottom Layer w5.3: U24.98@1023.85,1021.22 1023.85,985.75 1041.53,968.07 1085.37,968.07 v1(1105.9,947.54)
TM4C129_TDO: TP30.1 U24.97 | length 192.8
  Top Layer w5.3: v1(1150,947.13) 1150,946.57 1158.9,937.67 TP30.1@1158.9,919
  Bottom Layer w5.3: U24.97@1039.59,1021.22 1039.59,987.33 1048.25,978.67 1118.46,978.67 v1(1150,947.13)
TM4C129_TMS: TP28.1 U24.99 | length 131.8
  Top Layer w5.3: TP28.1@1053.9,920 v1(1053.9,948.54)
  Bottom Layer w5.3: U24.99@1008.1,1021.22 1008.1,974.48 1034.04,948.54 v1(1053.9,948.54)
TPS62913_1_EN_SYNC: R146.1 U29.1 | length 86
  Top Layer w10: U29.1@2510.33,931.84 2528.16,931.84 2545,915 v1(2545,905)
  Bottom Layer w10: v1(2545,905) 2546.68,906.68 R146.1@2578.71,906.68
TPS62913_1_FB: R153.1 R154.2 U29.9 | length 130.5
  Top Layer w10: U29.9@2485.73,905.26 2485.73,874.96 2472.33,861.57 R154.2@2472.33,830.3 R153.1@2522.33,830.3
TPS62913_1_NR_SS: C160.1 U29.8 | length 98.1
  Top Layer w10: C160.1@2412.84,833.18 2412.84,834.16 2426.54,847.86 2433.35,847.86 2466.04,880.56 U29.8@2466.04,905.26
TPS62913_1_SCONF: R148.2 U29.10 | length 127.9
  Top Layer w10: U29.10@2505.41,905.26 2505.41,886.62 2513.84,878.19 2526.49,878.19 2560,844.68 R148.2@2597.33,844.68
TPS62913_1_SW: L2.1 U29.2 | length 36.6
  Top Layer w10: U29.2@2503.45,951.52 2540,951.52
TPS62913_2_EN_SYNC: R156.1 U32.1 | length 86
  Top Layer w10: U32.1@2872.01,1564.46 2889.83,1564.46 2906.67,1547.62 v1(2906.67,1537.62)
  Bottom Layer w10: v1(2906.67,1537.62) 2908.35,1539.3 R156.1@2940.38,1539.3
TPS62913_2_FB: R162.1 R163.2 U32.9 | length 130.5
  Top Layer w10: U32.9@2847.4,1537.88 2847.4,1507.58 2834,1494.19 R163.2@2834,1462.92 R162.1@2884,1462.92
TPS62913_2_NR_SS: C177.1 U32.8 | length 97.5
  Top Layer w10: C177.1@2774.51,1465.8 2789.2,1480.48 2795.02,1480.48 2827.72,1513.18 U32.8@2827.72,1537.88
TPS62913_2_SCONF: R160.2 U32.10 | length 162.7
  Top Layer w10: U32.10@2867.09,1537.88 2867.09,1519.24 2875.52,1510.81 2941.39,1510.81 2956.47,1495.72 R160.2@2956.47,1450.85
TPS62913_2_SW: L3.1 U32.2 | length 36.6
  Top Layer w10: U32.2@2865.12,1584.14 2901.67,1584.14
TPS74801_1_BIAS: R150.2 U30.4 | length 83.3
  Top Layer w10: R150.2@5677.75,1067.63 5718.86,1108.75 U30.4@5744.01,1108.75
TPS74801_1_EN: R149.2 U30.5 | length 123.2
  Top Layer w10: R149.2@5677.75,1017.63 5699.82,1017.63 5712.84,1030.65 5712.84,1077.3 5724.6,1089.06 U30.5@5744.01,1089.06
TPS74801_1_FB: R151.1 R152.2 U30.8 | length 162.4
  Top Layer w10: U30.8@5854.25,1128.43 5903.33,1128.43 5914.13,1117.63 R152.2@5914.13,1085.98 R151.1@5980.51,1085.98
TPS74801_1_PG: R147.1 U30.3 | length 70.7
  Top Layer w10: R147.1@5677.75,1117.63 5688.55,1128.43 U30.3@5744.01,1128.43
TPS74801_1_SS: C166.1 U30.7 | length 64
  Top Layer w10: U30.7@5854.25,1108.75 5877.91,1108.75 5882.84,1103.83 v1(5885,1103.83)
  Bottom Layer w10: C166.1@5854.25,1104.81 5884.02,1104.81 v1(5885,1103.83)
TPS74801_2_BIAS: R158.2 U31.4 | length 83.3
  Top Layer w10: R158.2@5677.75,1486.82 5718.86,1527.94 U31.4@5744.01,1527.94
TPS74801_2_EN: R157.2 U31.5 | length 125.2
  Top Layer w10: R157.2@5677.75,1436.82 5703.29,1436.82 5712.84,1446.37 5712.84,1496.49 5724.6,1508.25 U31.5@5744.01,1508.25
TPS74801_2_FB: R159.1 R161.2 U31.8 | length 162.4
  Top Layer w10: U31.8@5854.25,1547.62 5903.33,1547.62 5914.13,1536.82 R161.2@5914.13,1505.17 R159.1@5980.51,1505.17
TPS74801_2_PG: R155.1 U31.3 | length 70.7
  Top Layer w10: R155.1@5677.75,1536.82 5688.55,1547.62 U31.3@5744.01,1547.62
TPS74801_2_SS: C178.1 U31.7 | length 64
  Top Layer w10: U31.7@5854.25,1527.94 5880.08,1527.94 v1(5885,1523.02)
  Bottom Layer w10: C178.1@5854.25,1524 5884.02,1524 v1(5885,1523.02)
TPS_CT: C109.1 U19.6 | length 64
  Top Layer w10: U19.6@1714.33,746.06 1755.2,746.06 C109.1@1771.58,729.69
TPS_VSYS_5V0_ON: R98.1 U19.3 U47.4 | length 1182.1
  Top Layer w8: U47.4@825.37,568.4 856.6,568.4 870,555 v1(870,502.5)
  Top Layer w10: v1(1620,520.76) 1620,664.65 1616.81,667.85 1616.81,735.48 1627.39,746.06 U19.3@1639.52,746.06
  SIG 1 w8: v1(870,502.5) 891.5,502.5 958.5,435.5 1098,435.5 1126,407.5 1292.5,407.5 1405.76,520.76 v1(1620,520.76)
TUSB_ADDR: TP5.1 U18.5 | length 56.5
  Top Layer w5.3: TP5.1@507.51,259.31 508.07,259.87 U18.5@508.07,315.56
TUSB_EN_N: R97.2 U18.11 | length 96.6
  Top Layer w5.3: U18.11@492.32,374.61 492.24,374.69 492.24,387.72 488.2,391.77 488.2,430.6 497.39,439.79 R97.2@523.29,439.79
TUSB_ID: TP3.1 U18.9 | length 199.6
  Top Layer w5.3: U18.9@523.82,374.61 523.9,374.69 523.9,387.72 536.18,400 584.4,400 621.55,437.15 TP3.1@621.55,505.45
TUSB_OUT: R299.1 U21.4 U47.1 | length 385.9
  Top Layer w10: U21.4@774.98,394.13 790.37,394.13 797.5,387 929,387 948,406 948,442.5 999.88,494.38 R299.1@999.88,512.5 977.5,512.5 958.6,493.6 U47.1@933.63,493.6
TUSB_OUT1: R89.2 R93.2 U21.1 | length 152.9
  Top Layer w5.3: R89.2@612.51,324.31 630.69,324.31 637.07,317.93 R93.2@669.95,317.93 696.07,317.93 705.97,308.03 727.47,308.03 735.61,316.17 U21.1@735.61,335.87
TUSB_OUT1_R: R89.1 U18.7 | length 52.7
  Top Layer w5.3: U18.7@525.79,337.21 543.62,337.21 556.48,324.35 R89.1@573.14,324.31 R89.1@573.14,324.31
TUSB_OUT2: R90.2 R92.2 U21.2 | length 181.4
  Top Layer w5.3: R90.2@612.51,364.41 634.16,364.41 650.82,381.07 R92.2@669.95,381.07 700,381.07 712.8,368.26 745,368.26 755.3,357.97 U21.2@755.3,335.87
TUSB_OUT2_R: R90.1 U18.8 | length 52.1
  Top Layer w5.3: U18.8@525.79,352.96 544.38,352.96 555.83,364.41 R90.1@573.14,364.41
TUSB_OUT3: R91.1 U18.6 | length 81.7
  Top Layer w5.3: U18.6@523.82,315.56 523.82,295 533.82,285 556.48,285 563.88,277.6 R91.1@563.88,263.69
TUSB_PORT: R95.2 U18.3 | length 57.8
  Top Layer w5.3: R95.2@420.03,312.6 422.98,315.56 U18.3@476.58,315.56
TUSB_VBUS_DET: R94.1 U18.4 | length 86.2
  Top Layer w5.3: R94.1@451.47,260.08 475.08,260.08 492.32,277.32 U18.4@492.32,315.56
USBTYPEC_CC1: J5.A5 U18.1 U20.4 U20.7 | length 844.8
  Top Layer w5.3: v1(435,357.97) 440.01,352.96 U18.1@474.61,352.96 ; U20.4@1018.85,453.43 U20.7@1018.85,420.56 1018.85,399.45 1027.76,390.54 v1(1027.76,390) 1055,390 1079.12,365.88 1079.12,312.74 J5.A5@1078.98,312.6
  SIG 1 w4.75: v1(435,357.97) 735,357.97 770.03,393 892.08,393 910.58,374.5 1012.26,374.5 v1(1027.76,390)
USBTYPEC_CC2: J5.B5 U18.2 U20.5 U20.6 | length 1073.6
  Top Layer w5.3: v1(395,357.97) 415.76,337.21 U18.2@474.61,337.21 ; J5.B5@1147.87,245.67 v1(1147.87,281.86)
  Top Layer w10: v1(990,395) 990,395.69 999.17,404.86 U20.6@999.17,420.56 U20.5@999.17,453.43
  SIG 1 w4.75: v1(395,357.97) 414.25,377.22 452.28,377.22 458.8,370.7 728.44,370.7 763.24,405.5 905.41,405.5 921,389.91 984.91,389.91 v1(990,395)
  Bottom Layer w8: v1(990,395) 977.49,382.49 977.49,333.64 1029.27,281.86 v1(1147.87,281.86)
VBUS_TYPEC_5V0: C102.1 C103.1 D1.2 J5.A4 J5.A9 J5.B4 J5.B9 L1.1 | length 218.1
  Top Layer w11: v1(1059.59,353) 1059.29,352.7 J5.A4@1059.29,312.6 1059.29,281.86 1069.13,272.02 J5.B9@1069.13,245.67 ; J5.B4@1167.56,245.67 1167.56,269.9 1177.4,279.74 J5.A9@1177.4,312.6 1177.4,348.15
  other v1: 1195,440.76 1235,440.76 1275,440.76 1115,480.76 1155,480.76 1195,480.76 1235,480.76 1275,480.76 1115,520.76 1155,520.76 1195,520.76 1235,520.76
VBUS_XDS_5V0: C227.1 C231.1 J34.1 R132.2 R136.2 TP23.1 U45.1 U45.2 U45.8 | length 1734.7
  Top Layer w12: v1(430.11,1102.74) 430.11,1053.63 U45.8@430.3,1053.44
  Top Layer w15: J34.1@161.81,992.9 212.95,992.9 v1(226.14,979.71)
  SIG 1 w12: v1(226.14,979.71) 227.28,978.56 227.28,973.46 v1(245.75,955) ; v1(430.11,1102.74) 414.87,1102.74 334.47,1183.14 308.39,1183.14 v1(275.25,1150) 266.14,1140.89 v1(266.14,979.71) 266.14,975.39 v1(245.75,955) ; v1(1250,1015) 1210,975 1210,953.5 1180.5,924 747,924 674.55,996.45 621.45,996.45 558.5,933.5 267.25,933.5 v1(245.75,955)
  Bottom Layer w12: R136.2@275.17,1121.06 275.17,1149.93 v1(275.25,1150) ; R132.2@1225.19,1014.22 1225.58,1014.61 1249.61,1014.61 v1(1250,1015)
VDD_AM263_1V2: C1.1 C2.1 C3.1 C19.2 C20.2 C21.2 C22.2 C29.2 C30.2 C31.2 C32.2 C39.2 C40.2 C41.2 C42.2 C44.2 C45.2 C46.2 C47.2 C49.1 C50.1 C51.1 C52.1 C53.1 C54.1 C55.1 C56.1 C157.1 C158.1 C159.1 L2.2 R153.2 TP10.1 U1.D10 U1.E9 U1.E11 U1.F9 U1.F11 U1.G5 U1.G6 U1.G13 U1.G14 U1.H3 U1.J15 U1.J16 U1.K5 U1.K6 U1.K13 U1.K14 U1.N5 U1.N6 U1.N13 U1.N14 U1.R9 U1.T4 U29.3 | length 1453.2
  Top Layer w10: U29.3@2510.33,971.21 2510.33,995.01 2516.7,1001.38
  Top Layer w15: R153.2@2522.33,783.06 2522.33,741.32 v1(2522.51,741.14) ; v1(3594.38,1178.07) U1.H3@3610.12,1162.32 ; v1(3625.87,894.61) U1.T4@3641.62,910.35 ; v1(3657.37,989.09) U1.N5@3673.12,1004.84 ; v1(3657.37,1083.58) U1.K5@3673.12,1099.33 ; v1(3657.37,1209.57) U1.G5@3673.12,1193.82 ; v1(3688.87,989.09) U1.N6@3704.61,1004.84 ; v1(3688.87,1083.58) U1.K6@3704.61,1099.33 ; v1(3688.87,1209.57) U1.G6@3704.61,1193.82 ; v1(3783.35,926.1) U1.R9@3799.1,941.85 ; v1(3783.35,1241.06) U1.F9@3799.1,1225.32 ; v1(3783.35,1272.56) U1.E9@3799.1,1256.81 ; U1.D10@3830.6,1288.31 v1(3846.35,1304.06) ; U1.F11@3862.09,1225.32 v1(3877.84,1241.06) ; U1.E11@3862.09,1256.81 v1(3877.84,1272.56) ; U1.N13@3925.09,1004.84 v1(3940.83,989.09) ; U1.K13@3925.09,1099.33 v1(3940.83,1083.58) ; U1.G13@3925.09,1193.82 v1(3940.83,1209.57) ; U1.N14@3956.58,1004.84 v1(3972.33,989.09) ; U1.K14@3956.58,1099.33 v1(3972.33,1083.58) ; U1.G14@3956.58,1193.82 v1(3972.33,1209.57) ; U1.J15@3988.08,1130.83 v1(4003.83,1146.57) ; U1.J16@4019.57,1130.83 v1(4035.32,1146.57)
  Bottom Layer w10: v1(3657.37,989.09) 3659.66,991.38 C56.1@3673,991.38 3686.58,991.38 v1(3688.87,989.09)
  Bottom Layer w12: C40.2@3395.44,1095.51 C40.2@3395.84,1095.92 ; C54.1@3654.78,1102.11 3654.78,1086.17 v1(3657.37,1083.58) ; v1(3657.37,1209.57) 3660.78,1206.15 C41.2@3673,1206.15 ; C41.2@3673,1206.06 C41.2@3673,1206.15 ; v1(3688.87,1083.58) 3693.17,1087.89 C46.2@3693.17,1102.11 ; v1(3688.87,1209.57) 3685.45,1206.15 C41.2@3673,1206.15 ; v1(3783.35,926.1) 3790.36,933.11 C50.1@3814.85,933.11 ; v1(3877.84,1241.06) 3878.91,1242.13 3878.91,1271.49 v1(3877.84,1272.56) ; C22.2@3927.21,1115.08 3927.21,1097.2 v1(3940.83,1083.58) 3950.53,1073.89 3962.64,1073.89 v1(3972.33,1083.58) ; v1(3940.83,989.09) 3943.94,985.99 3969.23,985.99 v1(3972.33,989.09) ; v1(3940.83,1209.57) 3944.25,1206.15 C19.2@3956.58,1206.15 ; C19.2@3956.58,1206.06 C19.2@3956.58,1206.15 ; v1(3972.33,1209.57) 3968.91,1206.15 C19.2@3956.58,1206.15 ; C55.1@4002.99,1115.08 4002.99,1145.74 v1(4003.83,1146.57)
  Bottom Layer w15: C2.1@3262.14,1012.28 3262.14,1045 3273.3,1056.16 v1(3288.51,1056.16) 3288.51,1056.97 3295,1063.46 C52.1@3295,1095.11 ; v1(3288.51,1295.92) C3.1@3288.51,1333.26 ; C1.1@3338.57,1012.28 3338.57,1048.08 3345.84,1055.35 v1(3345.84,1056.16) ; v1(3345.62,1295.92) 3345.62,1296.73 3348.24,1299.35 C42.2@3348.24,1339.3 ; C21.2@3395.62,1339.3 v1(3395.62,1295.92) 3395.84,1295.7 C44.2@3395.84,1247.05 ; v1(3395.84,1056.16) C40.2@3395.84,1095.92 ; C32.2@3445.84,1247.31 3445.84,1295.52 v1(3446.24,1295.92) C49.1@3446.24,1339.3 ; v1(3446.46,1056.16) C29.2@3446.46,1095.92 ; v1(3783.35,1241.06) 3784.17,1241.06 3785.66,1239.57 C31.2@3801.86,1239.57 ; v1(3783.35,1272.56) 3784.54,1273.75 C30.2@3802.01,1273.75
  other v1: 2572.18,1110.22 2622.18,1110.22 2672.19,1110.22 2722.19,1110.22 2572.18,1160.22 2622.18,1160.22 2672.19,1160.22 2722.19,1160.22 2572.18,1210.22 2622.18,1210.22 2672.19,1210.22 2722.19,1210.22
VDD_ETH1_1V1_FILT: C114.1 C115.1 C116.1 C117.1 C118.1 C119.1 C120.1 C121.1 FB3.2 U22.6 U22.31 U22.39 | length 624.7
  Top Layer w10: C120.1@6779.03,729.88 v1(6810,729.88)
  Top Layer w15: FB3.2@6215.25,1311.34 6274.72,1311.34 6283.04,1319.66 C115.1@6344,1319.66 6345.46,1321.12 v1(6375,1321.12) ; C119.1@6397.76,745.04 6412.91,729.88 v1(6440,729.88) 6440.57,730.46 6455.73,730.46 C118.1@6470.32,745.04 ; C116.1@6556.28,918.09 6586.71,918.09 v1(6590,921.38)
  Bottom Layer w10: v1(6440,729.88) U22.31@6491.32,729.88 ; U22.39@6556.28,853.9 C117.1@6556.28,921.46 ; 6556.28,886.71 C117.1@6556.28,921.46 ; v1(6590,921.38) 6589.92,921.46 C117.1@6556.28,921.46 ; U22.6@6759.03,729.88 v1(6810,729.88) C121.1@6846.59,729.88 ; 6791.84,729.88 6826.59,729.88
  other v1: 6397.76,1290.74 6420,1321.12
VDD_ETH1_2V5_FILT: C122.1 C123.1 C124.1 C125.1 C126.1 C127.1 FB4.2 U22.3 U22.9 | length 1183.3
  Top Layer w10: v1(6315,963.52) 6426.67,851.86 6751.7,851.86 6779.03,824.52 C126.1@6779.03,788.94 v1(6810,788.94) 6840,758.94 6840,700.83 v1(6810,670.83) C124.1@6779.03,670.83
  Top Layer w15: FB4.2@6142.49,970.9 6208.74,970.9 C122.1@6210,972.16 6218.63,963.52 C123.1@6280.09,963.52 v1(6315,963.52)
  Bottom Layer w10: U22.9@6759.03,670.83 6791.84,670.83 ; U22.3@6759.03,788.94 v1(6810,788.94) C127.1@6846.59,788.94 ; 6791.84,788.94 6826.59,788.94 ; 6826.59,670.83 6791.84,670.83 ; C125.1@6846.59,670.83 v1(6810,670.83) 6791.84,670.83
VDD_ETH2_1V1_FILT: C191.1 C192.1 C193.1 C194.1 C195.1 C196.1 C197.1 C198.1 FB5.2 U37.6 U37.31 U37.39 | length 559.8
  Top Layer w10: C197.1@6775.03,1679.88 v1(6810,1679.88)
  Top Layer w15: FB5.2@6215.25,1449.44 6274.72,1449.44 C191.1@6279,1453.72 6283.04,1457.76 C192.1@6344,1457.76 6345.46,1459.22 v1(6375,1459.22) ; C196.1@6402.76,1695.04 6417.91,1679.88 v1(6440,1679.88) 6458.71,1679.88 C195.1@6475.32,1696.49 ; C193.1@6556.28,1868.09 6586.71,1868.09 v1(6590,1871.38)
  Bottom Layer w10: v1(6440,1679.88) U37.31@6491.32,1679.88 ; U37.39@6556.28,1803.9 C194.1@6556.28,1871.46 6589.92,1871.46 v1(6590,1871.38) ; U37.6@6759.03,1679.88 v1(6810,1679.88) C198.1@6846.59,1679.88
  other v1: 6417.91,1455
VDD_ETH2_2V5_FILT: C199.1 C200.1 C201.1 C202.1 C203.1 C204.1 FB6.2 U37.3 U37.9 | length 1263
  Top Layer w10: FB6.2@6215.25,1188.64 6278.76,1188.64 C199.1@6278.93,1188.47 6300,1188.47 6309.86,1178.61 C200.1@6334,1178.61 6374.64,1178.61 v1(6375,1178.25) 6432.19,1235.44 6538.39,1235.44 6674.39,1371.44 6674.39,1499.1 6734.47,1559.19 6785.59,1559.19 6810,1583.6 v1(6810,1620.83) ; C203.1@6775.03,1738.94 v1(6810,1738.94) 6840,1708.94 6840,1650.83 v1(6810,1620.83) ; C201.1@6779.03,1620.83 v1(6810,1620.83)
  Bottom Layer w10: U37.9@6759.03,1620.83 v1(6810,1620.83) C202.1@6846.59,1620.83 ; U37.3@6759.03,1738.94 v1(6810,1738.94) C204.1@6846.59,1738.94
VDD_ETH_1V1: C175.1 C176.1 FB3.1 FB5.1 R159.2 TP11.1 U31.9 U31.10 | length 247.4
  Top Layer w10: U31.9@5854.25,1567.31 5883.12,1567.31 5890,1574.19 ; U31.10@5854.25,1586.99 5882.39,1586.99 5909.13,1613.73 C176.1@5909.13,1617.67
  Top Layer w15: FB3.1@6162.1,1310.55 FB5.1@6162.1,1449.44
VDD_ETH_2V5: C164.1 C165.1 FB4.1 FB6.1 R151.2 TP12.1 U30.9 U30.10 | length 331.6
  Top Layer w10: U30.9@5854.25,1148.12 5883.12,1148.12 5890,1155 ; U30.10@5854.25,1167.8 5882.39,1167.8 5909.13,1194.55 C165.1@5909.13,1198.48 ; v1(6082.5,1127.3) 6099.97,1144.77 6099.97,1159.88 6101.86,1161.77 6128.73,1188.64 FB6.1@6162.1,1188.64
  Top Layer w15: v1(6082.5,1077.3) 6082.5,1076.49 6089.34,1069.65 FB4.1@6089.34,970.9
VDD_XDS3V3: C139.2 C140.2 C141.2 C145.2 C146.1 C147.2 C148.1 C149.1 C150.2 C228.1 C232.1 C233.2 R138.2 R139.2 R140.2 R141.2 R142.2 R143.2 R144.2 R251.2 R311.2 R312.2 TP25.1 U24.7 U24.8 U24.16 U24.26 U24.28 U24.39 U24.47 U24.51 U24.52 U24.69 U24.79 U24.90 U24.101 U24.113 U24.122 U25.1 U26.8 U27.8 U45.3 U45.4 | length 1842.5
  Top Layer w7: U45.3@481.48,943.2 481.29,943.01 481.29,926.06 492.56,914.8 493.85,914.8
  Top Layer w8: v1(630.73,934.53) TP25.1@674.75,934.53
  Top Layer w12: R144.2@375.63,1204.12 375.63,1181.32 v1(389.15,1167.8) ; C145.2@518.94,1188.47 v1(550,1188.47) ; v1(540,1474.16) 507.96,1474.16 500.19,1481.93 500.19,1505.66 C150.2@504.12,1505.66 v1(540,1505.66) ; R251.2@631.97,1238.85 v1(631.97,1272.33) ; R311.2@645,1605.31 645.54,1604.77 645.54,1580.41 v1(646.08,1579.87) ; v1(646.08,973.57) 660,987.49 C232.1@660,1020.15 ; v1(680.73,1158.1) 680.73,1156.48 682.27,1154.94 C228.1@682.27,1124.76 ; v1(772.07,1579.87) R312.2@772.07,1607.95 ; C147.2@787.63,1044.84 v1(787.63,1077.56) ; v1(976.42,1068.87) 977.25,1068.04 977.25,1045.56 C146.1@977.49,1045.32 ; v1(1206.61,1697.01) 1210.55,1700.94 C141.2@1210.55,1723.86 U25.1@1285.36,1723.86 ; v1(1219.48,1085.27) 1219.48,1115.27 U27.8@1286.73,1115.27 ; v1(1223.41,1313.82) C140.2@1223.42,1340 U26.8@1286.73,1340
  Top Layer w15: v1(850.81,1579.87) C148.1@850.81,1607.63
  Bottom Layer w7: U24.7@492.35,1174.76 536.3,1174.76 v1(550,1188.47) 547.96,1190.51 U24.8@492.35,1190.51 ; U24.16@492.35,1316.5 v1@539.81,1316.5 ; U24.26@492.35,1473.98 v1@539.81,1473.98 ; U24.28@492.35,1505.47 v1@539.81,1505.47 ; v1@645.89,973.76 U24.122@645.89,1021.22 ; v1@645.89,1580.06 U24.39@645.89,1627.52 ; v1@771.88,1580.06 U24.47@771.88,1627.52 ; U24.113@787.63,1021.22 v1@787.63,1068.68 ; U24.51@834.87,1627.52 834.87,1585.19 840,1580.06 v1@850.62,1580.06 ; U24.52@850.62,1627.52 v1@850.62,1580.06 ; v1(850.81,1579.87) v1@850.62,1580.06 ; U24.101@976.6,1021.22 v1@976.6,1068.68 ; v1@1050,1174.76 U24.90@1098.65,1174.76 ; v1@1051.19,1505.47 U24.69@1098.65,1505.47 ; U24.79@1098.65,1347.99 C149.1@1166.88,1347.99 1170,1351.11 v1(1170,1375.91)
  Bottom Layer w8: v1@539.81,1316.5 v1(540,1316.68) ; v1@539.81,1473.98 v1(540,1474.16) ; v1@539.81,1505.47 v1(540,1505.66) ; v1@645.89,973.76 v1(646.08,973.57) ; v1@645.89,1580.06 v1(646.08,1579.87) ; v1@771.88,1580.06 v1(772.07,1579.87) ; v1@787.63,1068.68 v1(787.63,1077.56) ; v1(976.42,1068.87) v1@976.6,1068.68 ; v1(1049.81,1174.58) v1@1050,1174.76 ; v1(1051,1505.28) v1@1051.19,1505.47
  Bottom Layer w12: v1(963.57,1744.24) 963.7,1744.37 R141.2@992.24,1744.37 R140.2@1039.13,1744.37 ; R139.2@1093.35,1744.37 1121.89,1744.37 v1(1122.02,1744.5) ; v1(1206.61,1697.01) 1206.61,1657.08 R138.2@1207.31,1656.39 ; R143.2@1211.05,1476.93 R142.2@1211.05,1514.93 1211.41,1515.29 1233.79,1515.29 v1(1245,1526.5)
  other v1: 607.48,914.8 607.27,947.27
VDDA18_AM263_OSC_PLL: C38.1 FB2.2 U1.R4 | length 695
  Top Layer w10: v1(3625.87,926.1) U1.R4@3641.62,941.85
  SIG 1 w5: 3609.88,885.13 3609.88,910.11 v1(3625.87,926.1) 3641.87,910.11 3641.87,887.34 3626.37,871.84
  SIG 1 w8: 3609.88,839.51 3609.88,885.13
  SIG 1 w15: v1(3500,605) 3500,673.29 3560.5,733.79 3587.94,733.79 3624.83,770.68 3624.83,824.56 3609.88,839.51
  Bottom Layer w15: v1(3500,605) 3500,503.25 3517.23,486.02 C38.1@3531.39,486.02 3532.41,485 FB2.2@3594.44,485
VDDA_AM263_1V8_LDO: C33.1 C34.1 C35.1 C36.1 C37.1 FB2.1 S1.1 U1.R6 U1.R8 U1.R11 | length 1571.9
  Top Layer w15: v1(3688.87,926.1) U1.R6@3704.61,941.85 ; v1(3751.86,926.1) U1.R8@3767.61,941.85 ; U1.R11@3862.09,941.85 v1(3877.84,926.1)
  Top Layer w20: S1.1@3044.5,656.22 3104.45,656.22 v1(3112.52,648.15)
  SIG 1 w5: v1(3688.87,926.1) 3704.61,941.85 3767.61,941.85 ; 3698.11,869.25 3704.49,875.62 3704.49,910.48 ; v1(3751.86,926.1) 3767.61,941.85 ; v1(3877.84,926.1) 3862.09,941.85 3767.61,941.85
  SIG 1 w5.5: v1(3688.87,926.1) 3704.49,910.48
  SIG 1 w20: v1(3112.52,648.15) 3117.34,643.32 3360,643.32 3394.93,608.39 3394.93,535.07 3455.38,474.62 3580.83,474.62 3677.43,571.23 3677.43,608.39 v1(3678.01,608.97) ; v1(3678.01,663.97) 3678.01,850.65 3697.36,870
  Bottom Layer w12: v1@3676.49,708.97 C36.1@3712.76,708.97 ; v1(3678.01,663.97) 3683.01,658.97 C34.1@3712.76,658.97
  Bottom Layer w20: v1(3678.01,608.97) 3698.15,608.97 3707.39,599.73 C33.1@3707.39,569.08 ; v1(4104.69,740.75) C35.1@4139.44,740.75
  other v1: 3676.01,708.97
VDDA_AM263_3V3: C25.1 C26.1 C27.1 C28.1 FB1.2 U1.P7 U1.P9 U1.P11 | length 165.1
  Top Layer w15: v1(3720.36,957.6) U1.P7@3736.11,973.35 ; v1(3783.35,957.6) U1.P9@3799.1,973.35 ; U1.P11@3862.09,973.35 v1(3877.84,957.6)
  Bottom Layer w12: C26.1@3898.93,608.97 v1(3931.68,608.97) ; C27.1@3898.93,658.97 v1(3931.68,658.97) ; C28.1@3898.93,708.97 v1(3931.68,708.97)
VDDA_ETH1_1V8: TP7.1 U22.13 U22.48 | length 624.5
  Top Layer w12: TP7.1@6700.57,611.5 6700.82,611.24 6700.82,592.62 v1(6733.44,560) 6800.59,560 6870,629.41 6870,806.84 6795.28,881.56 v1(6762.73,881.56)
  Bottom Layer w12: v1(6733.44,560) U22.13@6733.44,586.18 ; U22.48@6733.44,853.9 6733.44,873.44 6741.56,881.56 v1(6762.73,881.56)
VDDA_ETH2_1V8: TP19.1 U37.13 U37.48 | length 545.8
  Top Layer w12: v1(6733.44,1510) 6737.35,1513.91 TP19.1@6779.03,1513.91 6811.27,1513.91 6875,1577.64 6875,1757.84 6817.84,1815 v1(6765,1815)
  Bottom Layer w12: v1(6733.44,1510) U37.13@6733.44,1536.18 ; U37.48@6733.44,1803.9 6753.9,1803.9 v1(6765,1815)
VDDC_XDS_1V0: C153.2 C154.2 C155.2 C156.1 U24.87 U24.115 | length 741.4
  Top Layer w12: v1(748.48,973) 748.48,944.73 C155.2@751.36,941.85
  Top Layer w15: v1(1049.81,1221.82) 1049.97,1221.67 1081.29,1221.67 C153.2@1081.38,1221.57 1085,1225.2 C156.1@1085,1270
  SIG 1 w12: v1(748.48,973) 790.48,1015 965,1015 1072.69,1122.69 1072.69,1198.95 v1(1049.81,1221.82)
  Bottom Layer w7: v1(748.48,973) 756.13,980.65 U24.115@756.13,1021.22 ; v1@1050,1222.01 U24.87@1098.65,1222.01
  Bottom Layer w8: v1(1049.81,1221.82) v1@1050,1222.01
  Bottom Layer w12: v1(748.48,973) 748.48,944.73 C154.2@751.36,941.85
